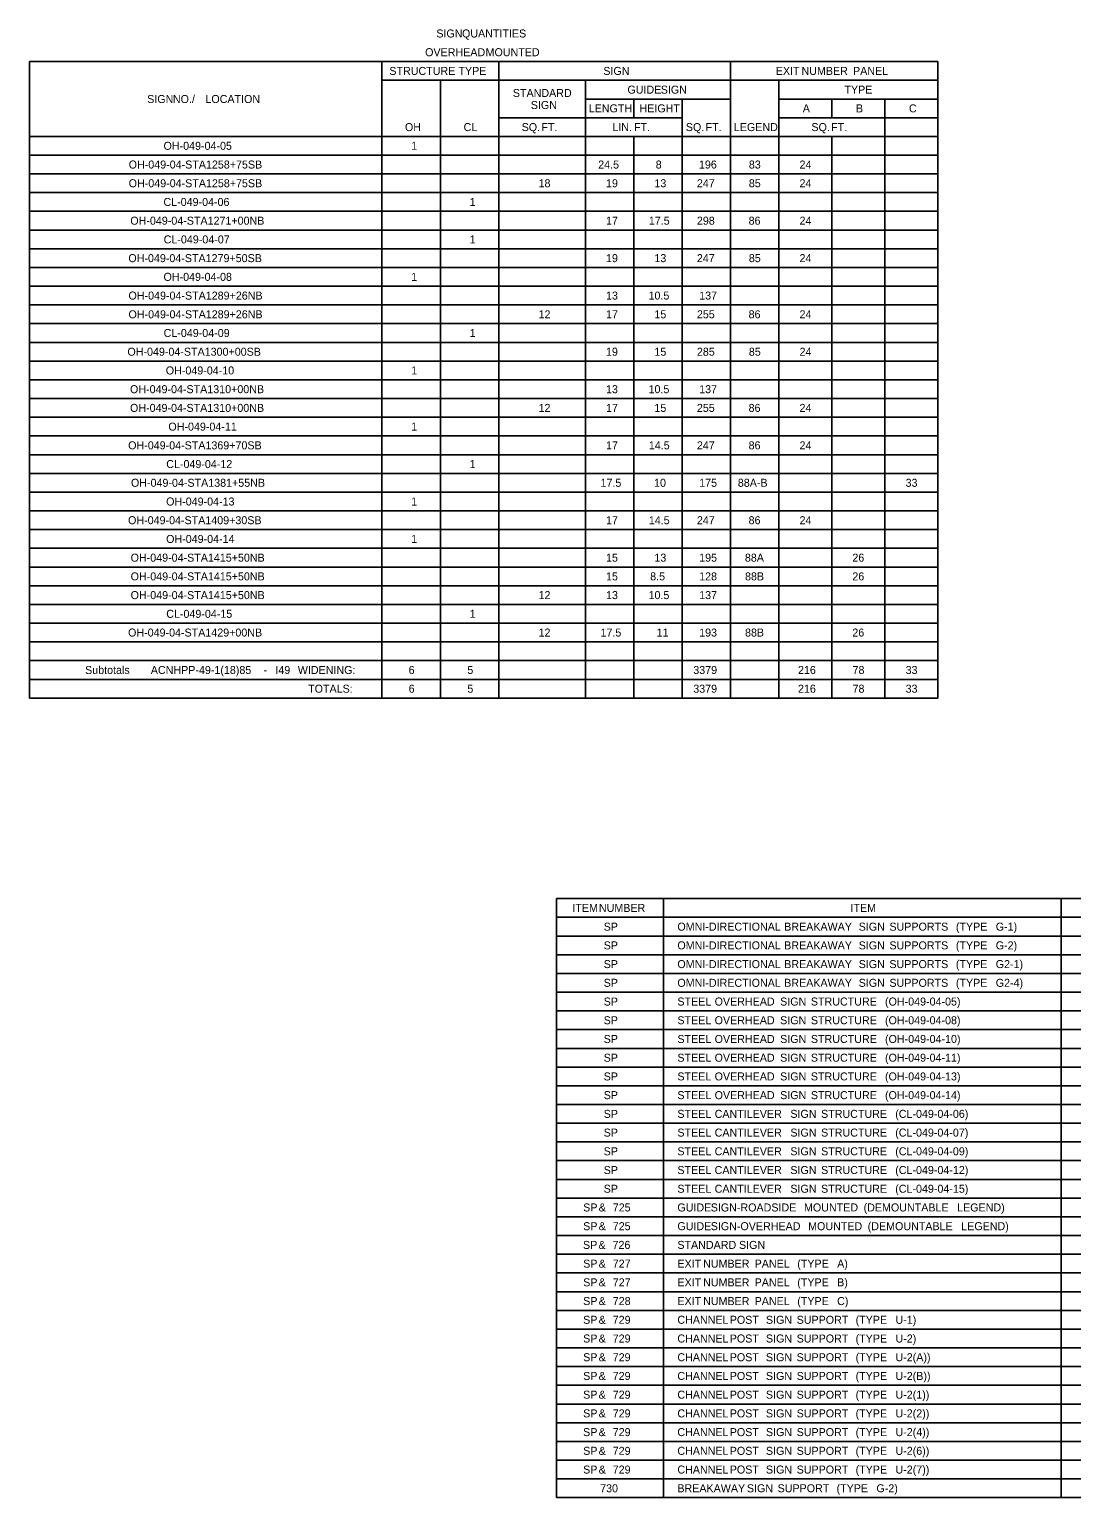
# Model space of a CAD drawing. Extents: x 1226631 to 1228126, y 151309 to 152305.
# Drawn here: x 1226631 to 1227282, y 151311 to 152229 of the extents above; entities that cross this region are included whole.
import ezdxf

# ---------------------------------------------------------------- set-up
doc = ezdxf.new("R2010")
doc.units = 0
doc.layers.add('R_Dimension', color=7, linetype='Continuous')

msp = doc.modelspace()

# ---------------------------------------------------------------- linework, layer by layer
at = {"layer": 'R_Dimension'}
for p, q in [((1226630.89, 152208.48), (1227198.83, 152208.48)), ((1226630.89, 151810.68), (1226630.89, 152208.48)), ((1226851.24, 151810.68), (1226851.24, 152208.48)), ((1226924.37, 151810.68), (1226924.37, 152208.48)), ((1227069.16, 151810.68), (1227069.16, 152208.48)), ((1227198.83, 151810.68), (1227198.83, 152208.48)), ((1226851.24, 152196.78), (1227198.83, 152196.78)), ((1226887.81, 151810.68), (1226887.81, 152196.78)), ((1226978.48, 151810.68), (1226978.48, 152196.78)), ((1227099.38, 151810.68), (1227099.38, 152196.78)), ((1226978.48, 152185.08), (1227069.16, 152185.08)), ((1227008.71, 152173.38), (1227008.71, 152185.08)), ((1227038.93, 151810.68), (1227038.93, 152185.08)), ((1227099.38, 152185.08), (1227198.83, 152185.08)), ((1227132.53, 152173.38), (1227132.53, 152185.08)), ((1227165.68, 151810.68), (1227165.68, 152185.08)), ((1226924.37, 152173.38), (1227038.93, 152173.38)), ((1227099.38, 152173.38), (1227198.83, 152173.38)), ((1226630.89, 152161.68), (1227198.83, 152161.68)), ((1227008.71, 151810.68), (1227008.71, 152161.68)), ((1227132.53, 151810.68), (1227132.53, 152161.68)), ((1226630.89, 152149.98), (1227198.83, 152149.98)), ((1226630.89, 152138.28), (1227198.83, 152138.28)), ((1226630.89, 152126.58), (1227198.83, 152126.58)), ((1226630.89, 152114.88), (1227198.83, 152114.88)), ((1226630.89, 152103.18), (1227198.83, 152103.18)), ((1226630.89, 152091.48), (1227198.83, 152091.48)), ((1226630.89, 152079.78), (1227198.83, 152079.78)), ((1226630.89, 152068.08), (1227198.83, 152068.08)), ((1226630.89, 152056.38), (1227198.83, 152056.38)), ((1226630.89, 152044.68), (1227198.83, 152044.68)), ((1226630.89, 152032.98), (1227198.83, 152032.98)), ((1226630.89, 152021.28), (1227198.83, 152021.28)), ((1226630.89, 152009.58), (1227198.83, 152009.58)), ((1226630.89, 151997.88), (1227198.83, 151997.88)), ((1226630.89, 151986.18), (1227198.83, 151986.18)), ((1226630.89, 151974.48), (1227198.83, 151974.48)), ((1226630.89, 151962.78), (1227198.83, 151962.78)), ((1226630.89, 151951.08), (1227198.83, 151951.08)), ((1226630.89, 151939.38), (1227198.83, 151939.38)), ((1226630.89, 151927.68), (1227198.83, 151927.68)), ((1226630.89, 151915.98), (1227198.83, 151915.98)), ((1226630.89, 151904.28), (1227198.83, 151904.28)), ((1226630.89, 151892.58), (1227198.83, 151892.58)), ((1226630.89, 151880.88), (1227198.83, 151880.88)), ((1226630.89, 151869.18), (1227198.83, 151869.18)), ((1226630.89, 151857.48), (1227198.83, 151857.48)), ((1226630.89, 151845.78), (1227198.83, 151845.78)), ((1226630.89, 151834.08), (1227198.83, 151834.08)), ((1226630.89, 151822.38), (1227198.83, 151822.38)), ((1226630.89, 151810.68), (1227198.83, 151810.68)), ((1226960.39, 151685.37), (1227737.95, 151685.37)), ((1226960.39, 151310.97), (1226960.39, 151685.37)), ((1227027.18, 151310.97), (1227027.18, 151685.37)), ((1227275.8, 151310.97), (1227275.8, 151685.37)), ((1226960.39, 151673.67), (1227737.95, 151673.67)), ((1226960.39, 151661.97), (1227737.95, 151661.97)), ((1226960.39, 151650.27), (1227737.95, 151650.27)), ((1226960.39, 151638.57), (1227737.95, 151638.57)), ((1226960.39, 151626.87), (1227737.95, 151626.87)), ((1226960.39, 151615.17), (1227737.95, 151615.17)), ((1226960.39, 151603.47), (1227737.95, 151603.47)), ((1226960.39, 151591.77), (1227737.95, 151591.77)), ((1226960.39, 151580.07), (1227737.95, 151580.07)), ((1226960.39, 151568.37), (1227737.95, 151568.37)), ((1226960.39, 151556.67), (1227737.95, 151556.67)), ((1226960.39, 151544.97), (1227737.95, 151544.97)), ((1226960.39, 151533.27), (1227737.95, 151533.27)), ((1226960.39, 151521.57), (1227737.95, 151521.57)), ((1226960.39, 151509.87), (1227737.95, 151509.87)), ((1226960.39, 151498.17), (1227737.95, 151498.17)), ((1226960.39, 151486.47), (1227737.95, 151486.47)), ((1226960.39, 151474.77), (1227737.95, 151474.77)), ((1226960.39, 151463.07), (1227737.95, 151463.07)), ((1226960.39, 151451.37), (1227737.95, 151451.37)), ((1226960.39, 151439.67), (1227737.95, 151439.67)), ((1226960.39, 151427.97), (1227737.95, 151427.97)), ((1226960.39, 151416.27), (1227737.95, 151416.27)), ((1226960.39, 151404.57), (1227737.95, 151404.57)), ((1226960.39, 151392.87), (1227737.95, 151392.87)), ((1226960.39, 151381.17), (1227737.95, 151381.17)), ((1226960.39, 151369.47), (1227737.95, 151369.47)), ((1226960.39, 151357.77), (1227737.95, 151357.77)), ((1226960.39, 151346.07), (1227737.95, 151346.07)), ((1226960.39, 151334.37), (1227737.95, 151334.37)), ((1226960.39, 151322.67), (1227737.95, 151322.67)), ((1226960.39, 151310.97), (1227737.95, 151310.97))]:
    msp.add_line(p, q, dxfattribs=at)

# ---------------------------------------------------------------- texts
for s, p in [('SIGN', (1226885.26, 152223.53)), (' QUANTITIES', (1226899.47, 152223.53)), ('OVERHEAD', (1226878.27, 152211.83)), (' MOUNTED', (1226914.21, 152211.83)), ('STRUCTURE', (1226855.9, 152200.13)), (' TYPE', (1226897.24, 152200.13)), ('SIGN', (1226989.66, 152200.13)), ('EXIT', (1227097.46, 152200.13)), (' NUMBER', (1227111.67, 152200.13)), (' PANEL', (1227143.88, 152200.13)), ('STANDARD', (1226933.1, 152186.33)), ('GUIDE', (1227004.72, 152188.43)), (' SIGN', (1227023.7, 152188.43)), ('TYPE', (1227140.37, 152188.43)), ('SIGN', (1226704.55, 152182.58)), (' NO./', (1226718.77, 152182.58)), (' LOCATION', (1226739.08, 152182.58)), ('SIGN', (1226944.32, 152178.83)), ('LENGTH', (1226980.52, 152176.73)), ('HEIGHT', (1227012.26, 152176.73)), ('A', (1227114.32, 152176.73)), ('B', (1227147.55, 152176.73)), ('C', (1227180.7, 152176.73)), ('OH', (1226865.67, 152165.03)), ('CL', (1226902.31, 152165.03)), ('SQ.', (1226938.61, 152165.03)), (' FT.', (1226949.08, 152165.03)), ('LIN.', (1226995.3, 152165.03)), (' FT.', (1227006.95, 152165.03)), ('SQ.', (1227041.23, 152165.03)), (' FT.', (1227051.7, 152165.03)), ('LEGEND', (1227071.26, 152165.03)), ('SQ.', (1227119.72, 152165.03)), (' FT.', (1227130.19, 152165.03)), ('OH-049-04-05', (1226714.77, 152153.33)), ('1', (1226869.53, 152153.33)), ('OH-049-04-STA1258+75SB', (1226692.98, 152141.63)), ('24.5', (1226986.47, 152141.63)), ('8', (1227022.4, 152141.63)), ('196', (1227049.42, 152141.63)), ('83', (1227080.61, 152141.63)), ('24', (1227112.3, 152141.63)), ('OH-049-04-STA1258+75SB', (1226692.98, 152129.93)), ('18', (1226949.18, 152129.93)), ('19', (1226991.33, 152129.93)), ('13', (1227021.58, 152129.93)), ('247', (1227048.14, 152129.93)), ('85', (1227080.61, 152129.93)), ('24', (1227112.3, 152129.93)), ('CL-049-04-06', (1226714.71, 152118.23)), ('1', (1226906.09, 152118.23)), ('OH-049-04-STA1271+00NB', (1226694, 152106.53)), ('17', (1226991.35, 152106.53)), ('17.5', (1227018.11, 152106.53)), ('298', (1227048.14, 152106.53)), ('86', (1227080.47, 152106.53)), ('24', (1227112.3, 152106.53)), ('CL-049-04-07', (1226714.85, 152094.83)), ('1', (1226906.09, 152094.83)), ('OH-049-04-STA1279+50SB', (1226692.78, 152083.13)), ('19', (1226991.33, 152083.13)), ('13', (1227021.58, 152083.13)), ('247', (1227048.14, 152083.13)), ('85', (1227080.61, 152083.13)), ('24', (1227112.3, 152083.13)), ('OH-049-04-08', (1226714.77, 152071.43)), ('1', (1226869.53, 152071.43)), ('OH-049-04-STA1289+26NB', (1226692.86, 152059.73)), ('13', (1226991.35, 152059.73)), ('10.5', (1227017.91, 152059.73)), ('137', (1227049.56, 152059.73)), ('OH-049-04-STA1289+26NB', (1226692.86, 152048.03)), ('12', (1226949.18, 152048.03)), ('17', (1226991.35, 152048.03)), ('15', (1227021.58, 152048.03)), ('255', (1227048.14, 152048.03)), ('86', (1227080.47, 152048.03)), ('24', (1227112.3, 152048.03)), ('CL-049-04-09', (1226714.83, 152036.33)), ('1', (1226906.09, 152036.33)), ('OH-049-04-STA1300+00SB', (1226692.19, 152024.63)), ('19', (1226991.33, 152024.63)), ('15', (1227021.58, 152024.63)), ('285', (1227048.14, 152024.63)), ('85', (1227080.61, 152024.63)), ('24', (1227112.3, 152024.63)), ('OH-049-04-10', (1226716.17, 152012.93)), ('1', (1226869.53, 152012.93)), ('OH-049-04-STA1310+00NB', (1226693.81, 152001.23)), ('13', (1226991.35, 152001.23)), ('10.5', (1227017.91, 152001.23)), ('137', (1227049.56, 152001.23)), ('OH-049-04-STA1310+00NB', (1226693.81, 151989.53)), ('12', (1226949.18, 151989.53)), ('17', (1226991.35, 151989.53)), ('15', (1227021.58, 151989.53)), ('255', (1227048.14, 151989.53)), ('86', (1227080.47, 151989.53)), ('24', (1227112.3, 151989.53)), ('OH-049-04-11', (1226717.8, 151977.83)), ('1', (1226869.53, 151977.83)), ('OH-049-04-STA1369+70SB', (1226692.66, 151966.13)), ('17', (1226991.35, 151966.13)), ('14.5', (1227018.11, 151966.13)), ('247', (1227048.14, 151966.13)), ('86', (1227080.47, 151966.13)), ('24', (1227112.3, 151966.13)), ('CL-049-04-12', (1226716.46, 151954.43)), ('1', (1226906.09, 151954.43)), ('OH-049-04-STA1381+55NB', (1226694.4, 151942.73)), ('17.5', (1226987.89, 151942.73)), ('10', (1227021.36, 151942.73)), ('175', (1227049.56, 151942.73)), ('88A-B', (1227073.74, 151942.73)), ('33', (1227178.6, 151942.73)), ('OH-049-04-13', (1226716.38, 151931.03)), ('1', (1226869.53, 151931.03)), ('OH-049-04-STA1409+30SB', (1226692.59, 151919.33)), ('17', (1226991.35, 151919.33)), ('14.5', (1227018.11, 151919.33)), ('247', (1227048.14, 151919.33)), ('86', (1227080.47, 151919.33)), ('24', (1227112.3, 151919.33)), ('OH-049-04-14', (1226716.38, 151907.63)), ('1', (1226869.53, 151907.63)), ('OH-049-04-STA1415+50NB', (1226694.2, 151895.93)), ('15', (1226991.35, 151895.93)), ('13', (1227021.58, 151895.93)), ('195', (1227049.56, 151895.93)), ('88A', (1227078.15, 151895.93)), ('26', (1227145.31, 151895.93)), ('OH-049-04-STA1415+50NB', (1226694.2, 151884.23)), ('15', (1226991.35, 151884.23)), ('8.5', (1227018.94, 151884.23)), ('128', (1227049.56, 151884.23)), ('88B', (1227078.23, 151884.23)), ('26', (1227145.31, 151884.23)), ('OH-049-04-STA1415+50NB', (1226694.2, 151872.53)), ('12', (1226949.18, 151872.53)), ('13', (1226991.35, 151872.53)), ('10.5', (1227017.91, 151872.53)), ('137', (1227049.56, 151872.53)), ('CL-049-04-15', (1226716.46, 151860.83)), ('1', (1226906.09, 151860.83)), ('OH-049-04-STA1429+00NB', (1226692.59, 151849.13)), ('12', (1226949.18, 151849.13)), ('17.5', (1226987.89, 151849.13)), ('11', (1227022.99, 151849.13)), ('193', (1227049.56, 151849.13)), ('88B', (1227078.23, 151849.13)), ('26', (1227145.31, 151849.13)), ('Subtotals', (1226665.73, 151825.73)), (' ACNHPP-49-1(18)85', (1226704.95, 151825.73)), (' -', (1226775.38, 151825.73)), (' I49', (1226782.82, 151825.73)), (' WIDENING:', (1226796.83, 151825.73)), ('6', (1226867.97, 151825.73)), ('5', (1226904.67, 151825.73)), ('3379', (1227045.88, 151825.73)), ('216', (1227111.33, 151825.73)), ('78', (1227145.45, 151825.73)), ('33', (1227178.6, 151825.73)), ('TOTALS:', (1226805.14, 151814.03)), ('6', (1226867.97, 151814.03)), ('5', (1226904.67, 151814.03)), ('3379', (1227045.88, 151814.03)), ('216', (1227111.33, 151814.03)), ('78', (1227145.45, 151814.03)), ('33', (1227178.6, 151814.03)), ('ITEM', (1226970.32, 151677.02)), (' NUMBER', (1226985.05, 151677.02)), ('ITEM', (1227144.13, 151677.02)), ('SP', (1226989.87, 151665.32)), ('OMNI-DIRECTIONAL', (1227035.95, 151665.32)), (' BREAKAWAY', (1227100.84, 151665.32)), (' SIGN', (1227147.41, 151665.32)), (' SUPPORTS', (1227166.62, 151665.32)), (' (TYPE', (1227208.16, 151665.32)), (' G-1)', (1227233.08, 151665.32)), ('SP', (1226989.87, 151653.62)), ('OMNI-DIRECTIONAL', (1227035.95, 151653.62)), (' BREAKAWAY', (1227100.84, 151653.62)), (' SIGN', (1227147.41, 151653.62)), (' SUPPORTS', (1227166.62, 151653.62)), (' (TYPE', (1227208.16, 151653.62)), (' G-2)', (1227233.08, 151653.62)), ('SP', (1226989.87, 151641.92)), ('OMNI-DIRECTIONAL', (1227035.95, 151641.92)), (' BREAKAWAY', (1227100.84, 151641.92)), (' SIGN', (1227147.41, 151641.92)), (' SUPPORTS', (1227166.62, 151641.92)), (' (TYPE', (1227208.16, 151641.92)), (' G2-1)', (1227233.08, 151641.92)), ('SP', (1226989.87, 151630.22)), ('OMNI-DIRECTIONAL', (1227035.95, 151630.22)), (' BREAKAWAY', (1227100.84, 151630.22)), (' SIGN', (1227147.41, 151630.22)), (' SUPPORTS', (1227166.62, 151630.22)), (' (TYPE', (1227208.16, 151630.22)), (' G2-4)', (1227233.08, 151630.22)), ('SP', (1226989.87, 151618.52)), ('STEEL', (1227035.95, 151618.52)), (' OVERHEAD', (1227057.37, 151618.52)), (' SIGN', (1227098.32, 151618.52)), (' STRUCTURE', (1227117.53, 151618.52)), (' (OH-049-04-05)', (1227163.87, 151618.52)), ('SP', (1226989.87, 151606.82)), ('STEEL', (1227035.95, 151606.82)), (' OVERHEAD', (1227057.37, 151606.82)), (' SIGN', (1227098.32, 151606.82)), (' STRUCTURE', (1227117.53, 151606.82)), (' (OH-049-04-08)', (1227163.87, 151606.82)), ('SP', (1226989.87, 151595.12)), ('STEEL', (1227035.95, 151595.12)), (' OVERHEAD', (1227057.37, 151595.12)), (' SIGN', (1227098.32, 151595.12)), (' STRUCTURE', (1227117.53, 151595.12)), (' (OH-049-04-10)', (1227163.87, 151595.12)), ('SP', (1226989.87, 151583.42)), ('STEEL', (1227035.95, 151583.42)), (' OVERHEAD', (1227057.37, 151583.42)), (' SIGN', (1227098.32, 151583.42)), (' STRUCTURE', (1227117.53, 151583.42)), (' (OH-049-04-11)', (1227163.87, 151583.42)), ('SP', (1226989.87, 151571.72)), ('STEEL', (1227035.95, 151571.72)), (' OVERHEAD', (1227057.37, 151571.72)), (' SIGN', (1227098.32, 151571.72)), (' STRUCTURE', (1227117.53, 151571.72)), (' (OH-049-04-13)', (1227163.87, 151571.72)), ('SP', (1226989.87, 151560.02)), ('STEEL', (1227035.95, 151560.02)), (' OVERHEAD', (1227057.37, 151560.02)), (' SIGN', (1227098.32, 151560.02)), (' STRUCTURE', (1227117.53, 151560.02)), (' (OH-049-04-14)', (1227163.87, 151560.02)), ('SP', (1226989.87, 151548.32)), ('STEEL', (1227035.95, 151548.32)), (' CANTILEVER', (1227057.37, 151548.32)), (' SIGN', (1227104.7, 151548.32)), (' STRUCTURE', (1227123.91, 151548.32)), (' (CL-049-04-06)', (1227170.25, 151548.32)), ('SP', (1226989.87, 151536.62)), ('STEEL', (1227035.95, 151536.62)), (' CANTILEVER', (1227057.37, 151536.62)), (' SIGN', (1227104.7, 151536.62)), (' STRUCTURE', (1227123.91, 151536.62)), (' (CL-049-04-07)', (1227170.25, 151536.62)), ('SP', (1226989.87, 151524.92)), ('STEEL', (1227035.95, 151524.92)), (' CANTILEVER', (1227057.37, 151524.92)), (' SIGN', (1227104.7, 151524.92)), (' STRUCTURE', (1227123.91, 151524.92)), (' (CL-049-04-09)', (1227170.25, 151524.92)), ('SP', (1226989.87, 151513.22)), ('STEEL', (1227035.95, 151513.22)), (' CANTILEVER', (1227057.37, 151513.22)), (' SIGN', (1227104.7, 151513.22)), (' STRUCTURE', (1227123.91, 151513.22)), (' (CL-049-04-12)', (1227170.25, 151513.22)), ('SP', (1226989.87, 151501.52)), ('STEEL', (1227035.95, 151501.52)), (' CANTILEVER', (1227057.37, 151501.52)), (' SIGN', (1227104.7, 151501.52)), (' STRUCTURE', (1227123.91, 151501.52)), (' (CL-049-04-15)', (1227170.25, 151501.52)), ('SP', (1226977.07, 151489.82)), (' &', (1226984.91, 151489.82)), (' 725', (1226993.69, 151489.82)), ('GUIDE', (1227035.95, 151489.82)), (' SIGN-ROADSIDE', (1227054.93, 151489.82)), (' MOUNTED', (1227113.24, 151489.82)), (' (DEMOUNTABLE', (1227150.48, 151489.82)), (' LEGEND)', (1227208.95, 151489.82)), (' (DEMOUNTABLE', (1227153.04, 151478.12)), (' LEGEND)', (1227211.51, 151478.12)), ('SP', (1226977.07, 151478.12)), (' &', (1226984.91, 151478.12)), (' 725', (1226993.69, 151478.12)), ('GUIDE', (1227035.95, 151478.12)), (' SIGN-OVERHEAD', (1227054.93, 151478.12)), (' MOUNTED', (1227115.8, 151478.12)), ('SP', (1226976.94, 151466.42)), (' &', (1226984.77, 151466.42)), (' 726', (1226993.55, 151466.42)), ('STANDARD', (1227035.95, 151466.42)), (' SIGN', (1227072.61, 151466.42)), ('SP', (1226977.07, 151454.72)), (' &', (1226984.91, 151454.72)), (' 727', (1226993.69, 151454.72)), ('EXIT', (1227035.95, 151454.72)), (' NUMBER', (1227050.17, 151454.72)), (' PANEL', (1227082.37, 151454.72)), (' (TYPE', (1227109.03, 151454.72)), (' A)', (1227133.95, 151454.72)), ('SP', (1226977.07, 151443.02)), (' &', (1226984.91, 151443.02)), (' 727', (1226993.69, 151443.02)), ('EXIT', (1227035.95, 151443.02)), (' NUMBER', (1227050.17, 151443.02)), (' PANEL', (1227082.37, 151443.02)), (' (TYPE', (1227109.03, 151443.02)), (' B)', (1227133.95, 151443.02)), ('SP', (1226977.07, 151431.32)), (' &', (1226984.91, 151431.32)), (' 728', (1226993.69, 151431.32)), ('EXIT', (1227035.95, 151431.32)), (' NUMBER', (1227050.17, 151431.32)), (' PANEL', (1227082.37, 151431.32)), (' (TYPE', (1227109.03, 151431.32)), (' C)', (1227133.95, 151431.32)), ('SP', (1226977.05, 151419.62)), (' &', (1226984.89, 151419.62)), (' 729', (1226993.67, 151419.62)), ('CHANNEL', (1227035.95, 151419.62)), (' POST', (1227066.82, 151419.62)), (' SIGN', (1227089.42, 151419.62)), (' SUPPORT', (1227108.63, 151419.62)), (' (TYPE', (1227145.48, 151419.62)), (' U-1)', (1227170.4, 151419.62)), ('SP', (1226977.05, 151407.92)), (' &', (1226984.89, 151407.92)), (' 729', (1226993.67, 151407.92)), ('CHANNEL', (1227035.95, 151407.92)), (' POST', (1227066.82, 151407.92)), (' SIGN', (1227089.42, 151407.92)), (' SUPPORT', (1227108.63, 151407.92)), (' (TYPE', (1227145.48, 151407.92)), (' U-2)', (1227170.4, 151407.92)), ('SP', (1226977.05, 151396.22)), (' &', (1226984.89, 151396.22)), (' 729', (1226993.67, 151396.22)), ('CHANNEL', (1227035.95, 151396.22)), (' POST', (1227066.82, 151396.22)), (' SIGN', (1227089.42, 151396.22)), (' SUPPORT', (1227108.63, 151396.22)), (' (TYPE', (1227145.48, 151396.22)), (' U-2(A))', (1227170.4, 151396.22)), ('SP', (1226977.05, 151384.52)), (' &', (1226984.89, 151384.52)), (' 729', (1226993.67, 151384.52)), ('CHANNEL', (1227035.95, 151384.52)), (' POST', (1227066.82, 151384.52)), (' SIGN', (1227089.42, 151384.52)), (' SUPPORT', (1227108.63, 151384.52)), (' (TYPE', (1227145.48, 151384.52)), (' U-2(B))', (1227170.4, 151384.52)), ('SP', (1226977.05, 151372.82)), (' &', (1226984.89, 151372.82)), (' 729', (1226993.67, 151372.82)), ('CHANNEL', (1227035.95, 151372.82)), (' POST', (1227066.82, 151372.82)), (' SIGN', (1227089.42, 151372.82)), (' SUPPORT', (1227108.63, 151372.82)), (' (TYPE', (1227145.48, 151372.82)), (' U-2(1))', (1227170.4, 151372.82)), ('SP', (1226977.05, 151361.12)), (' &', (1226984.89, 151361.12)), (' 729', (1226993.67, 151361.12)), ('CHANNEL', (1227035.95, 151361.12)), (' POST', (1227066.82, 151361.12)), (' SIGN', (1227089.42, 151361.12)), (' SUPPORT', (1227108.63, 151361.12)), (' (TYPE', (1227145.48, 151361.12)), (' U-2(2))', (1227170.4, 151361.12)), ('SP', (1226977.05, 151349.42)), (' &', (1226984.89, 151349.42)), (' 729', (1226993.67, 151349.42)), ('CHANNEL', (1227035.95, 151349.42)), (' POST', (1227066.82, 151349.42)), (' SIGN', (1227089.42, 151349.42)), (' SUPPORT', (1227108.63, 151349.42)), (' (TYPE', (1227145.48, 151349.42)), (' U-2(4))', (1227170.4, 151349.42)), ('SP', (1226977.05, 151337.72)), (' &', (1226984.89, 151337.72)), (' 729', (1226993.67, 151337.72)), ('CHANNEL', (1227035.95, 151337.72)), (' POST', (1227066.82, 151337.72)), (' SIGN', (1227089.42, 151337.72)), (' SUPPORT', (1227108.63, 151337.72)), (' (TYPE', (1227145.48, 151337.72)), (' U-2(6))', (1227170.4, 151337.72)), ('SP', (1226977.05, 151326.02)), (' &', (1226984.89, 151326.02)), (' 729', (1226993.67, 151326.02)), ('CHANNEL', (1227035.95, 151326.02)), (' POST', (1227066.82, 151326.02)), (' SIGN', (1227089.42, 151326.02)), (' SUPPORT', (1227108.63, 151326.02)), (' (TYPE', (1227145.48, 151326.02)), (' U-2(7))', (1227170.4, 151326.02)), ('730', (1226987.66, 151314.32)), ('BREAKAWAY', (1227035.95, 151314.32)), (' SIGN', (1227077.53, 151314.32)), (' SUPPORT', (1227096.74, 151314.32)), (' (TYPE', (1227133.59, 151314.32)), (' G-2)', (1227158.51, 151314.32))]:
    msp.add_text(s, height=5, dxfattribs=at).set_placement(p)

doc.saveas('drawing.dxf')
